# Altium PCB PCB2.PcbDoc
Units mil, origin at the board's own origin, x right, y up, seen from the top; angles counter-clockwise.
Board outline 954.83 x 957.14 mil, 2 copper layers (Top Layer, Bottom Layer); 36 components, 33 nets, 168 pads, 2 vias.
Unrouted connection lines stored in the file: 90.
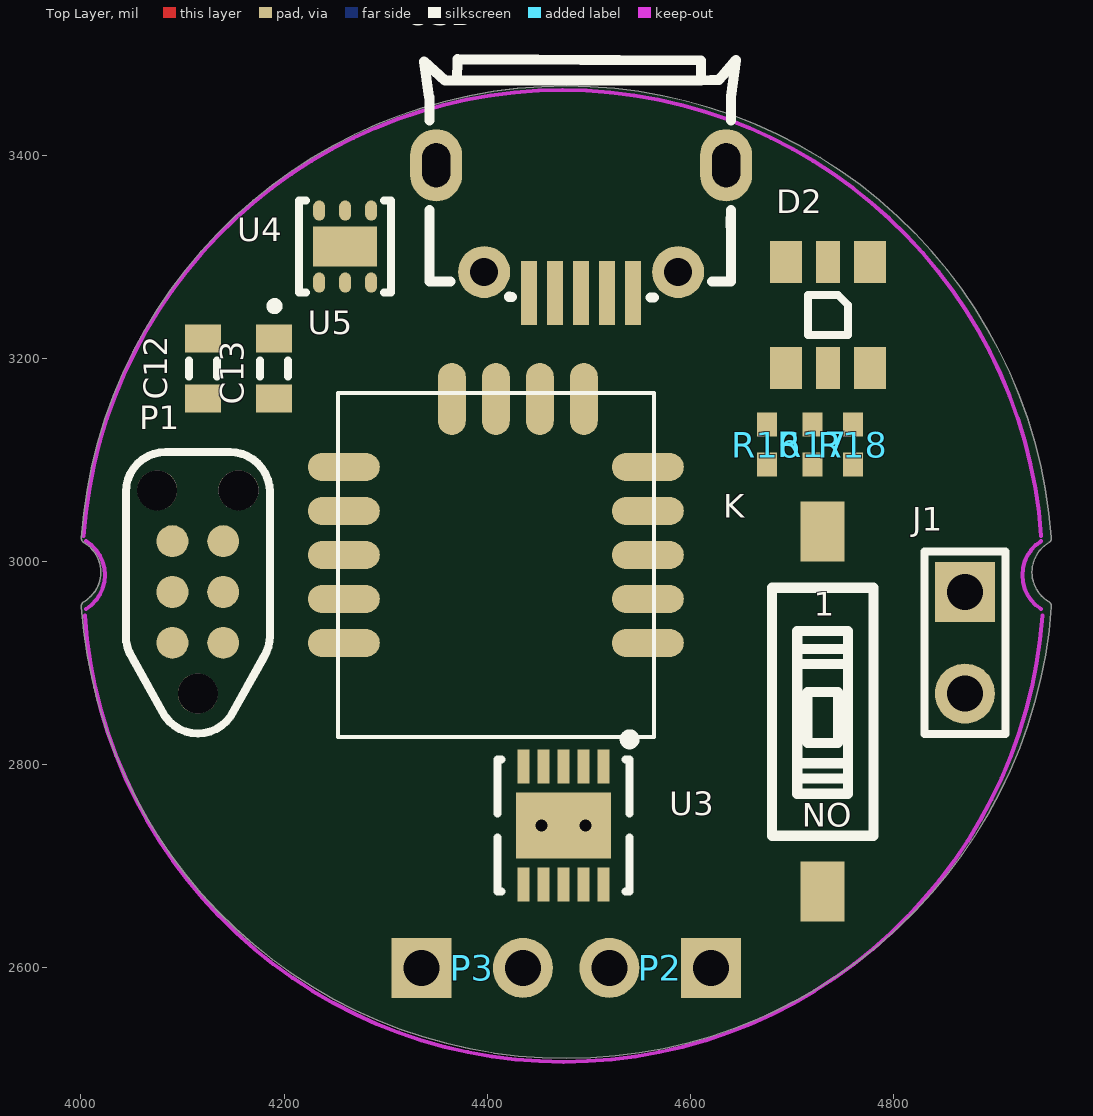
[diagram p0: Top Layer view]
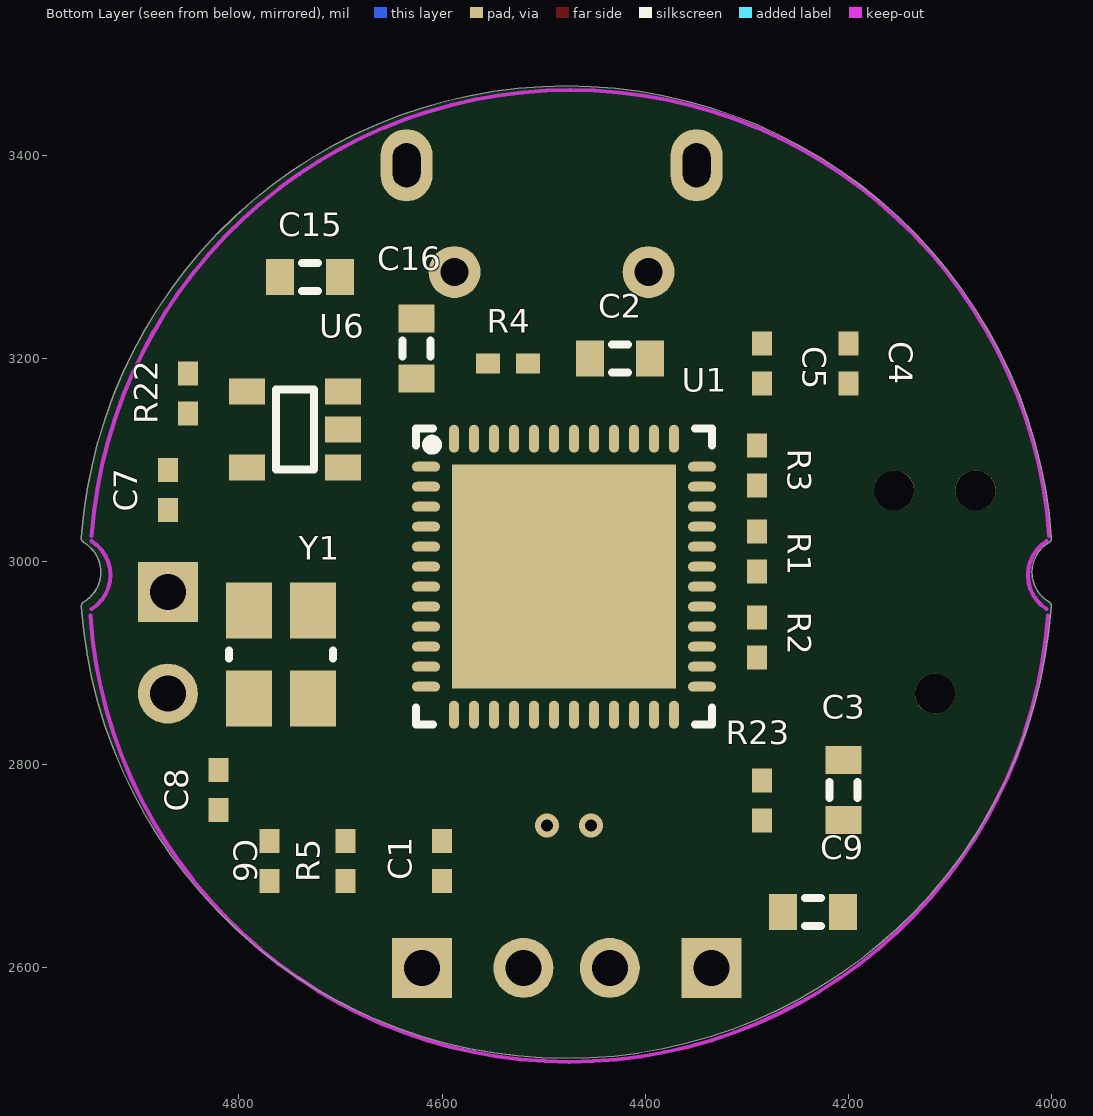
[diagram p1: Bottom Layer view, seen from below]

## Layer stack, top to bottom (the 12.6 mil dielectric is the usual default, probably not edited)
Top Solder: solder mask 0.4, Solder Resist, Dk 3.5
Top Layer: signal copper 1.4
Dielectric 1: dielectric 12.6, FR-4, Dk 4.8
Bottom Layer: signal copper 1.4
Bottom Solder: solder mask 0.4, Solder Resist, Dk 3.5

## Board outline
4000.38,2955.11 cw(c4005.32,2955.99) 4002.77,2960.31 ccw(c3985.59,2989.47) 4019.43,2989.47 ccw(c3985.59,2989.47) 4002.8,3018.61 cw(c4005.35,3022.93) 4000.34,3023.28 cw(c4477.72,2989.47) 4955.05,3023.82 4955.13,3022.94 cw(c4950.12,3022.94) 4952.66,3018.62 ccw(c4969.84,2989.47) 4952.64,2960.33 cw(c4950.09,2956.01) 4955.11,2956.01 4955.09,2955.65 cw(c4477.72,2989.47)

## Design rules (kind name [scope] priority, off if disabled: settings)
Clearance [All] p1: gap=5 ignorepadtopadclearanceinfootprint=FALSE
PolygonConnect [All] p1: connectstyle=Relief reliefconductorwidth=10 reliefentries=4 polygonreliefangle="90 Angle" airgapwidth=10
RoutingVias [All] p1: holewidth=28 width=50 viastyle="Through Hole" minholewidth=28 minwidth=50 maxholewidth=28 maxwidth=50
SolderMaskExpansion [All] p1: expansion=4 istentingtop=FALSE
Width [All] p1: maxlimit=10 minlimit=10 preferedwidth=10
30 further rules are at their usual default settings.

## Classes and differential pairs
net class RGBLED[1..3]: RGBLED1 RGBLED2 RGBLED3
net class MOTOR_CONTROL[1..4]: MOTOR_CONTROL1 MOTOR_CONTROL2 MOTOR_CONTROL3 MOTOR_CONTROL4

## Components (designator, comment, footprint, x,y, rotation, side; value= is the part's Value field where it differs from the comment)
C1 "10nF" 0402 4600,2705.31 r90 bottom
C2 "1uF" 0603 4425,3200 r180 bottom
C3 "4.7uF" 0603 4205,2775 r270 bottom
C4 "100nF" 0402 4200,3195 r270 bottom
C5 "100nF" 0402 4285,3195 r270 bottom
C6 "100nF" 0402 4770,2705.32 r270 bottom
C7 "22pF" 0402 4870,3070.31 r90 bottom
C8 "22pF" 0402 4820,2775 r90 bottom
C9 "10uF" 0603 4235,2655 r180 bottom
C12 "1uF" 0603 4120,3190 r90 top
C13 "1uF" 0603 4190,3190 r270 top
C15 "4.7uF" 0603 4730,3280 r0 bottom
C16 "4.7uF" 0603 4625,3209.53 r270 bottom
D2 "SMLVN6RGB1W1" "3.5x2.8 mm 6-SMD" 4735,3242.83 r270 top
J1 "78171-0002" HDR1*2 4870,2920 r0 top
K "2.54-1P-PGT" SW-SMD_2P-L6.2-LS9.4 4730.07,2846.81 r270 top
P1 "TC2030-IDC-NL" TC2030-IDC-NL 4115,2970 r90 top
P2 "HEADER 2X1 0.05\" UNPOLARIZED" HDR1*2 4570,2600 r270 top
P3 "HEADER 2X1 0.05\" UNPOLARIZED" HDR1*2 4385,2600 r90 top
R1 "22R" 0402 4290,3010 r270 bottom
R2 "22R" 0402 4290,2925.32 r270 bottom
R3 "22R" 0402 4290,3094.68 r90 bottom
R4 "100K" 0402 4535,3195 r180 bottom
R5 "100K" 0402 4695,2705.31 r90 bottom
R16 "22.6R" 0402 4675,3115 r90 top
R17 "130R" 0402 4720,3115 r90 top
R18 "24.9R" 0402 4760,3115 r90 top
R22 "10K" 0402 4850,3165.31 r90 bottom
R23 "100K" 0402 4285,2765 r270 bottom
U1 "STM32F051C8U6" QFN50P700X700X60_HS-49L 4480,2985 r180 bottom
U3 "A3901SEJTR-T" DFN50P300X300X75_HS-11N 4475,2740 r180 top
U4 "ADP122ACPZ-3.3-R7" "LFCSP-6 2.0X2.0X0.55" 4260,3310 r0 top
U5 "DX-BT24-T" DX-BT24-T 4408.31,2996.61 r180 top
U6 "MCP73831T-2ACI/OT" SOT-23-OT5_L 4745,3130 r0 bottom
USB "MicroXNJ" MICRO-USB-SMD_MICROXNJ 4492.29,3327.15 r180 top
Y1 "7V-16.000MAAE-T" "3.2x2.5 CRYSTAL" 4758.5,2908.31 r270 bottom

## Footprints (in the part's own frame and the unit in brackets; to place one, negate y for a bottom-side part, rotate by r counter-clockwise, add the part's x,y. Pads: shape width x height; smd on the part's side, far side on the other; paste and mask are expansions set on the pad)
"3.2x2.5 CRYSTAL" [mm]
  rect 1.4x1.15 smd: 1(-1.1,-0.8) 2(1.1,-0.8) 3(1.1,0.8) 4(-1.1,0.8)
  silkscreen extent -0.1,-1.3 0.1,1.3, body extent -1.6,-1.25 1.6,1.25, height 0.8
"3.5x2.8 mm 6-SMD" [mm] "3.5 x 2.8 mm 6-SMD Flat Leads"
  rect 1.05x0.8 smd: 1(-1.325,1.05) 3(-1.325,-1.05) 4(1.325,-1.05) 6(1.325,1.05)
  rect 1.05x0.6 smd: 2(-1.325,0) 5(1.325,0)
  silkscreen extent -0.5,-0.5 0.5,0.5, body extent -1.75,-1.4 1.75,1.4, height 0.6
0402 [mm] "Chip Body 1.0 x 0.5 mm (LxW typ)"
  rect 0.6x0.5 smd: 1(-0.5,0) 2(0.5,0)
  body extent -0.55,-0.3 0.55,0.3, height 0.55
0603 [mm] "Chip Body 1.6 x 0.8 mm (LxW typ)"
  rect 0.7x0.9 smd: 1(-0.75,0) 2(0.75,0)
  silkscreen extent -0.2,-0.35 0.2,0.35, body extent -0.85,-0.48 0.85,0.48, height 0.9
DFN50P300X300X75_HS-11N [mm]
  rect 0.3x0.85 smd: 1(-1,-1.475) 2(-0.5,-1.475) 3(0,-1.475) 4(0.5,-1.475) 5(1,-1.475) 6(1,1.475) 7(0.5,1.475) 8(0,1.475) 9(-0.5,1.475) 10(-1,1.475)
  rect 2.38x1.65 smd: 11(0,0)
  silkscreen extent -1.78,-2.28 1.65,1.65, body extent -1.5,-1.5 1.5,1.5, height 0.75
DX-BT24-T [mm] "DX-BT24-T"
  oval 1.8x0.7 smd: 1(-3.8,1.95) 2(-3.8,0.85) 2(3.8,-2.45) 3(-3.8,-0.25) 3(3.8,0.85) 4(-3.8,-1.35) 5(-3.8,-2.45) 11(3.8,-1.35) 12(3.8,-0.25) 14(3.8,1.95)
  oval 0.7x1.8 smd: 6(-2.2,-4.15) 7(-1.1,-4.15) 8(0,-4.15) 9(1.1,-4.15)
  silkscreen extent -3.95,-4.3 3.95,4.3
HDR1*2 [mm]
  rect 1.5x1.5 hole 0.9: 1(0,1.27)
  round 1.5 hole 0.9: 2(0,-1.27)
  silkscreen extent -1.02,-2.29 1.02,2.29
"LFCSP-6 2.0X2.0X0.55" [mm] ". 6-Lead Lead Frame Chip Scale Package [LFCSP_UD]  2.00 mm?2.00 mm Body, Ultra Thin, Dual Lead  (CP-6-3)"
  oval 0.3x0.5 smd: 1(-0.65,-0.9) 2(0,-0.9) 3(0.65,-0.9) 4(0.65,0.9) 5(0,0.9) 6(-0.65,0.9)
  rect 1.6x1 smd: 7(0,0)
  silkscreen extent -1.86,-1.59 1.15,1.15, body extent -1,-1 1,1, height 0.6
MICRO-USB-SMD_MICROXNJ [mm]
  rect 0.4x1.6 smd paste-100 mask+0.051: 1(-1.3,1.596) 2(-0.65,1.596) 3(0,1.596) 4(0.65,1.596) 5(1.3,1.596)
  round 1.3 hole 0.7: 6(2.425,1.074) 9(-2.425,1.074)
  oval 1.3x1.8 hole 0.7 slot 1.1 at 90 deg: 7(3.625,-1.596) 8(-3.625,-1.596)
  silkscreen extent -3.87,-4.24 3.93,1.71
QFN50P700X700X60_HS-49L [mm] "QFN, 48-Leads, Body 7,00x7,00mm, Pitch 0,50mm, Thermal Pad 5,60x5,60mm, IPC High Density"
  oval 0.7x0.25 smd: 1(-3.45,2.75) 2(-3.45,2.25) 3(-3.45,1.75) 4(-3.45,1.25) 5(-3.45,0.75) 6(-3.45,0.25) 7(-3.45,-0.25) 8(-3.45,-0.75) 9(-3.45,-1.25) 10(-3.45,-1.75) 11(-3.45,-2.25) 12(-3.45,-2.75) 25(3.45,-2.75) 26(3.45,-2.25) 27(3.45,-1.75) 28(3.45,-1.25) 29(3.45,-0.75) 30(3.45,-0.25) 31(3.45,0.25) 32(3.45,0.75) 33(3.45,1.25) 34(3.45,1.75) 35(3.45,2.25) 36(3.45,2.75)
  oval 0.25x0.7 smd: 13(-2.75,-3.45) 14(-2.25,-3.45) 15(-1.75,-3.45) 16(-1.25,-3.45) 17(-0.75,-3.45) 18(-0.25,-3.45) 19(0.25,-3.45) 20(0.75,-3.45) 21(1.25,-3.45) 22(1.75,-3.45) 23(2.25,-3.45) 24(2.75,-3.45) 37(2.75,3.45) 38(2.25,3.45) 39(1.75,3.45) 40(1.25,3.45) 41(0.75,3.45) 42(0.25,3.45) 43(-0.25,3.45) 44(-0.75,3.45) 45(-1.25,3.45) 46(-1.75,3.45) 47(-2.25,3.45) 48(-2.75,3.45)
  rect 5.6x5.6 smd: 49(0,0)
  silkscreen extent -3.7,-3.7 3.7,3.7, body extent -3.55,-3.55 3.55,3.55, height 0.6
SOT-23-OT5_L [mm] "SOT23, 5-Leads, Body 2.9x1.6mm, Pitch 0.95mm, Lead Span 2.7mm, IPC High Density"
  rect 0.9x0.65 smd: 1(-1.2,0.95) 2(-1.2,0) 3(-1.2,-0.95) 4(1.2,-0.95) 5(1.2,0.95)
  silkscreen extent -0.47,-1 0.47,1, body extent -0.9,-1.55 0.9,1.55, height 1.45
SW-SMD_2P-L6.2-LS9.4 [mm]
  rect 1.5x1.1 smd paste+0 mask+0.051: 1(-4.636,-0.002) 2(4.364,-0.002)
  silkscreen extent -3.24,-1.27 2.96,1.27
TC2030-IDC-NL [mm] "TagConnector TC2030-IDC-NL"
  round 0.8 smd paste-1: 1(-1.27,-0.635) 2(-1.27,0.635) 3(0,-0.635) 4(0,0.635) 5(1.27,-0.635) 6(1.27,0.635)
  round 1 hole 1 unplated mask+0: ""(-2.54,0) ""(2.54,-1.016) ""(2.54,1.016)
  Top Layer pour cut-out: -1.27,-0.085 -1.27,0.085 -1.06,0.127 -0.881,0.246 -0.762,0.425 -0.72,0.635 -0.72,0.635 -0.55,0.635 -0.496,0.396 -0.343,0.205 -0.122,0.099 0.122,0.099 0.343,0.205 0.496,0.396 0.55,0.635 0.55,0.635 0.72,0.635 0.762,0.425 0.881,0.246 1.06,0.127 1.27,0.085 1.27,0.085 1.27,-0.085 1.06,-0.127 0.881,-0.246 0.762,-0.425 0.72,-0.635 0.72,-0.635 0.55,-0.635 0.496,-0.396 0.343,-0.205 0.122,-0.099 -0.122,-0.099 -0.343,-0.205 -0.496,-0.396 -0.55,-0.635 -0.55,-0.635 -0.72,-0.635 -0.762,-0.425 -0.881,-0.246 -1.06,-0.127 -1.27,-0.085
  silkscreen extent -3.54,-1.8 3.5,1.8, body extent -1.67,-1.03 1.67,1.03, height 0

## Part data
C1: "10nF 0402 X7R 25V ±5%", Supplier Part Number 1=1692285
C2 C12 C13: "1uF 0603 X5R 10V ±10%", Supplier Part Number 1=1759399
C3 C15 C16: "4.7uF 0603 X5R 10V ±10%", Supplier Part Number 1=2362098
C4 C5 C6: "100nF 0402 X7R 16V ±10%", Supplier Part Number 1=1288252
C7 C8: "22pF 0402 NP0/CG0 50V ±5%", Supplier Part Number 1=1414580
C9: "10uF 0603 X5R 6.3V ±20%", Supplier Part Number 1=2456110
D2: "ROHM SMLVN6RGB1W1 LED Tri-Color Blue/Green/Red Chip LED 6-Pin 1411 T/RLED Tri-Color Blue/Green/Red Chip LED 6-Pin 1411", Supplier Part Number 1=755-SMLVN6RGB1W1
J1: "Molex Pico-EZmate™ Wire-to-Board Header, 2 contacts", Supplier Part Number 1=2313710
P1: "TagConnect TC2030-IDC-NL SWD Programming Connector"
R1 R2 R3: "22R 0402 1/16W ±1%", Supplier Part Number 1=2072797
R4 R5 R23: "100K 0402 1/16W ±1%", Supplier Part Number 1=2072519
R16: "22.6R 0402 1/16W ±0.05R", Supplier Part Number 1=2302454
R17: "130R 0402 1/16W ±0.05R", Supplier Part Number 1=2059115
R18: "24.9R 0402 1/16W ±0.05R", Supplier Part Number 1=2059102
R22: "10K 0402 1/16W ±1%", Supplier Part Number 1=2072517
U1: "STMICROELECTRONICS  STM32F051C8U6  MCU 32BIT CORTEX-M0 48MHZ UFQFPN-48", Supplier Part Number 1=2393638
U3: "ALLEGRO MICROSYSTEMS - A3901SEJTR-T - IC, MOTOR DRIVER", Supplier Part Number 1=1651947
U4: "Analog Devices ADP122ACPZ-3.3-R7 - 5.5 V Input, 300 mA, Low Quiescent  Current, CMOS Linear Regulator", Supplier Part Number 1=2457164
U6: "Miniature Single-Cell, Fully Integrated Li-Ion, Li-Polymer Charge Management Controller, 4.2V, 5-Pin SOT-23, Industrial Temperature, Tape and Reel", Supplier Part Number 1=1332158
USB: Core Colour=黑色, Current Rating - Power (Max)=1.8A, JLCPCB Part Class="Extended Part", LCSC Part Name="Micro-B 母 卧贴", Manufacturer="SHOU HAN(首韩)", Operating Temperature Range=-20℃~+85℃, Rated Voltage (Max)=30V
Y1: "TXC - 7V-16.000MAAE-T, 16MHZ, 30PPM, 12PF - CRYSTAL", Supplier Part Number 1=887-1462-1-ND

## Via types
v1: diameter 23.62, hole 11.81, Top Layer to Bottom Layer, 2 vias

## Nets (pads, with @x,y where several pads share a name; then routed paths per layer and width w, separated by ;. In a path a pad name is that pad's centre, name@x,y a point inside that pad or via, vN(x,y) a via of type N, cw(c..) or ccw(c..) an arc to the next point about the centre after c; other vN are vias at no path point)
+3.3V: C1.2 C2.2 C3.2 C4.2 C5.2 C9.2 C13.2 D2.1 D2.2 D2.3 P1.1 R5.2 R23.2 U1.9 U1.24 U1.48 U3.8 U4.1 U5.8
+5: C15.2 U6.4 USB.1
BT_RX: U1.43 U5.2@4557.91,2963.15
BT_TX: U1.42 U5.11
CHARGING: R23.1 U1.26 U6.1
GND: C1.1 C2.1 C3.1 C4.1 C5.1 C6.1 C7.1 C8.1 C9.1 C12.1 C13.1 C15.1 C16.1 J1.2 P1.5 R4.1 R22.2 U1.8 U1.23 U1.47 U1.49 U3.3 U3.11 U4.2 U4.3 U4.5 U4.7 U5.14 U6.2 USB.5 Y1.2 Y1.4
  other v1: 4453.35,2740 4496.65,2740
IMU_INT: U1.25
MCU_X1_16MHZ: C7.2 U1.5 Y1.1
MCU_X2_16MHZ: C8.2 U1.6 Y1.3
MOTOR_CONTROL1: U1.10 U3.1
MOTOR_CONTROL2: U1.11 U3.2
MOTOR_CONTROL3: U1.12 U3.4
MOTOR_CONTROL4: U1.13 U3.5
NetC12_2: C12.2 K.2 U4.4 U4.6
NetD2_4: D2.4 R16.2
NetD2_5: D2.5 R17.2
NetD2_6: D2.6 R18.2
NetP1_2: P1.2 R1.2
NetP1_3: P1.3 R2.2
NetP1_4: P1.4 R3.2
NetP2_1: P2.1 U3.10
NetP2_2: P2.2 U3.9
NetP3_1: P3.1 U3.6
NetP3_2: P3.2 U3.7
NetR4_2: R4.2 U1.44
NetR22_1: R22.1 U6.5
NRST: C6.2 R2.1 R5.1 U1.7
RGBLED1: R17.1 U1.31
RGBLED2: R16.1 U1.32
RGBLED3: R18.1 U1.30
SWCLK: R3.1 U1.37
SWDIO: R1.1 U1.34
VBAT: C16.2 J1.1 K.1 U1.1 U6.3
pads on no net: P1. P1.6 U1.2 U1.3 U1.4 U1.14 U1.15 U1.16 U1.17 U1.18 U1.19 U1.20 U1.21 U1.22 U1.27 U1.28 U1.29 U1.33 U1.35 U1.36 U1.38 U1.39 U1.40 U1.41 U1.45 U1.46 U5.1 U5.2@4258.7,3093.07 U5.3 U5.4 U5.5 U5.6 U5.7 U5.9 U5.12 USB.2 USB.3 USB.4 USB.6 USB.7 USB.8 USB.9

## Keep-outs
Keep-Out Layer:
  lines w3.94: 4002.48,3025 cw(c4473.74,2991.63) 4945,3025 ; 4003.74,2946.63 ccw(c4475,2980) 4946.26,2946.63 ; 4005,2953.23 ccw(c3984.13,2986.62) 4005,3020 ; 4945,2953.23 cw(c4965.87,2986.62) 4945,3020

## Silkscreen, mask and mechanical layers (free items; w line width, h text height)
Mechanical 2:
  lines w10: 4005.32,2955.99 ccw(c3985.59,2989.47) 4005.35,3022.93 cw(c4477.72,2989.47) 4950.09,3023 ; 4005.35,2955.94 ccw(c4477.72,2989.47) 4950.09,2956.01 cw(c4969.84,2989.47) 4950.12,3022.94
Mechanical 10:
  lines w3.94: 4005,3025 cw(c4476.26,2991.63) 4947.52,3025 ; 4003.82,2955.9 ccw(c4475.08,2989.27) 4946.34,2955.9 ; 4003.82,2955.89 ccw(c3982.95,2989.27) 4003.82,3022.65 ; 4003.82,2955.89 ccw(c3982.95,2989.27) 4003.82,3022.65 ; 4003.82,2955.9 ccw(c4475.08,2989.27) 4946.34,2955.9 ; 4003.82,3022.64 cw(c4475.08,2989.27) 4946.34,3022.64 ; 4003.82,3022.64 cw(c4475.08,2989.27) 4946.34,3022.64 ; 4008.82,2955.89 ccw(c3987.95,2989.27) 4008.82,3022.65 ; 4008.82,2955.9 ccw(c4480.08,2989.27) 4951.34,2955.9 ; 4008.82,2955.9 ccw(c4480.08,2989.27) 4951.34,2955.9 ; 4008.82,2955.89 ccw(c3987.95,2989.27) 4008.82,3022.65 ; 4008.82,3022.64 cw(c4480.08,2989.27) 4951.34,3022.64 ; 4008.82,3022.64 cw(c4480.08,2989.27) 4951.34,3022.64 ; 4946.34,2955.89 cw(c4967.21,2989.27) 4946.34,3022.65 ; 4946.34,2955.89 cw(c4967.21,2989.27) 4946.34,3022.65 ; 4951.34,2955.89 cw(c4972.21,2989.27) 4951.34,3022.65 ; 4951.34,2955.89 cw(c4972.21,2989.27) 4951.34,3022.65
